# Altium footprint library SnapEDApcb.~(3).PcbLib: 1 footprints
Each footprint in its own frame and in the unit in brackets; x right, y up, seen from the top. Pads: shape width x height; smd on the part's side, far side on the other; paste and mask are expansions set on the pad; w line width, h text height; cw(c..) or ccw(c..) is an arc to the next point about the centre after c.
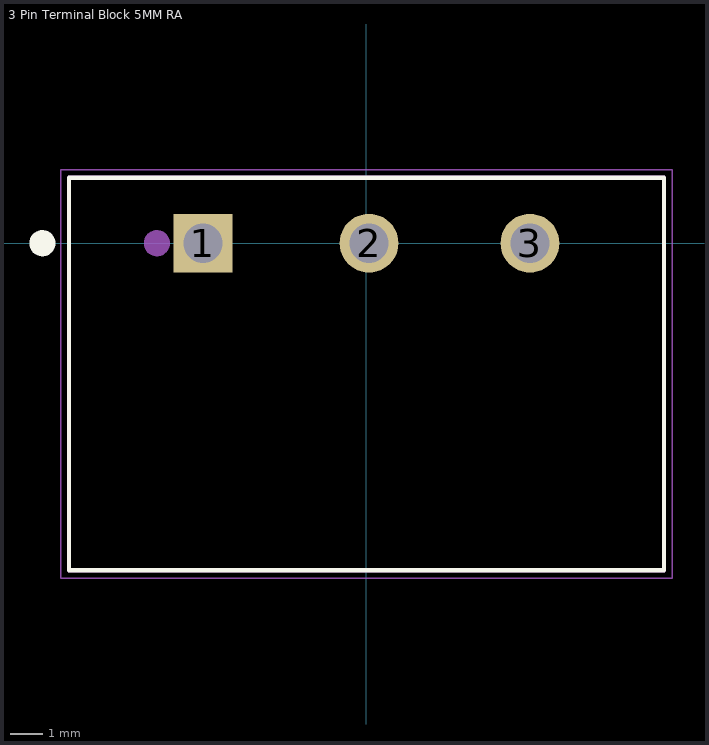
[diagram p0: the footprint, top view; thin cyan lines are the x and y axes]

## 3 Pin Terminal Block 5MM RA [mm] "3 Pin Terminal Block HDR 5MM THT RA 231-433_001-000"
pads (3):
  rect 1.8x1.8 hole 1.2: 1(-5,0)
  round 1.8 hole 1.2: 2(0.08,0) 3(5,0)
Top Overlay:
  circle w0.4: c-9.91,0 r0.2
  lines w0.127: -9.1,-10 9.1,-10 9.1,2 -9.1,2 -9.1,-10
Mechanical 13:
  circle w0.4: c-6.41,0 r0.2
  lines w0.127: -9.1,-10 -9.1,2 9.1,2 9.1,-10 -9.1,-10
Mechanical 15:
  lines w0.05: -9.35,-10.25 9.35,-10.25 9.35,2.25 -9.35,2.25 -9.35,-10.25
3D body "2342079-3--3DModel-STEP-1.STEP": height 8.97, standoff -2.28, extent -8.418,-10.064 8.382,1.936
